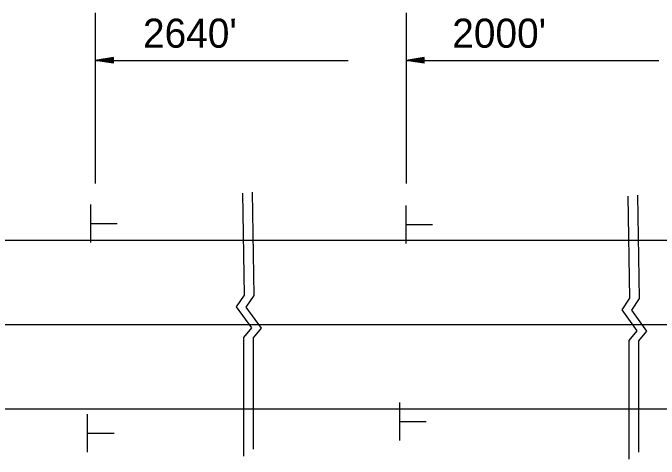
# Model space of a CAD drawing. Extents: x 13528 to 25043, y 7635 to 10612.
# Drawn here: x 16041.5 to 16174.9, y 10266.3 to 10358.4 of the extents above; entities that cross this region are included whole.
import ezdxf

# ---------------------------------------------------------------- set-up
doc = ezdxf.new("R2010")
doc.units = 0
doc.layers.add('Default', color=7, linetype='Continuous')

msp = doc.modelspace()

# ---------------------------------------------------------------- linework, layer by layer
at = {"layer": 'Default'}
for p, q in [((16058.47, 10358.39), (16058.47, 10323.18)), ((16122.63, 10358.39), (16122.63, 10323.18)), ((16062.22, 10349.16), (16058.47, 10348.6)), ((16058.47, 10348.6), (16110.66, 10348.6)), ((16062.22, 10348.04), (16058.47, 10348.6)), ((16062.22, 10349.07), (16059.1, 10348.6)), ((16062.22, 10348.13), (16059.1, 10348.6)), ((16062.22, 10348.97), (16059.74, 10348.6)), ((16062.22, 10348.23), (16059.74, 10348.6)), ((16062.22, 10348.88), (16060.37, 10348.6)), ((16062.22, 10348.32), (16060.37, 10348.6)), ((16062.22, 10348.78), (16061, 10348.6)), ((16062.22, 10348.42), (16061, 10348.6)), ((16062.22, 10348.69), (16061.63, 10348.6)), ((16062.22, 10348.51), (16061.63, 10348.6)), ((16062.22, 10348.04), (16062.22, 10349.16)), ((16126.38, 10349.16), (16122.63, 10348.6)), ((16122.63, 10348.6), (16174.82, 10348.6)), ((16126.38, 10348.04), (16122.63, 10348.6)), ((16126.38, 10349.07), (16123.26, 10348.6)), ((16126.38, 10348.13), (16123.26, 10348.6)), ((16126.38, 10348.97), (16123.9, 10348.6)), ((16126.38, 10348.23), (16123.9, 10348.6)), ((16126.38, 10348.88), (16124.53, 10348.6)), ((16126.38, 10348.32), (16124.53, 10348.6)), ((16126.38, 10348.78), (16125.16, 10348.6)), ((16126.38, 10348.42), (16125.16, 10348.6)), ((16126.38, 10348.69), (16125.79, 10348.6)), ((16126.38, 10348.51), (16125.79, 10348.6)), ((16126.38, 10348.04), (16126.38, 10349.16)), ((16057.56, 10311.04), (16057.56, 10318.87)), ((16122.63, 10310.81), (16122.63, 10318.63)), ((16057.68, 10314.94), (16063.02, 10314.94)), ((16122.75, 10314.7), (16128.09, 10314.7)), ((16020.49, 10311.48), (16082.46, 10311.48)), ((16082.46, 10311.48), (16143.31, 10311.48)), ((16143.31, 10311.48), (16229.91, 10311.48)), ((16020.95, 10294.1), (16082.12, 10294.1)), ((16082.12, 10294.1), (16143.31, 10294.1)), ((16143.31, 10294.1), (16229.91, 10294.1)), ((16121.37, 10270.17), (16121.37, 10277.99)), ((16021.41, 10276.71), (16081.79, 10276.71)), ((16081.79, 10276.71), (16156.13, 10276.71)), ((16143.31, 10276.71), (16239.09, 10276.71)), ((16056.88, 10267.78), (16056.88, 10275.61)), ((16121.48, 10274.06), (16126.82, 10274.06)), ((16057, 10271.67), (16062.34, 10271.67))]:
    msp.add_line(p, q, dxfattribs=at)
for points in [[(16088.89, 10321.19), (16089.21, 10300.15), (16087.58, 10297.74), (16090.75, 10293.41), (16089.08, 10291.41), (16089.08, 10266.95)], [(16090.88, 10321.38), (16091.21, 10300.07), (16089.58, 10297.66), (16092.75, 10293.33), (16091.08, 10291.33), (16091.08, 10268.36)], [(16168.45, 10320.56), (16168.77, 10299.52), (16167.15, 10297.11), (16170.31, 10292.78), (16168.65, 10290.78), (16168.64, 10266.32)], [(16170.45, 10320.75), (16170.77, 10299.44), (16169.15, 10297.03), (16172.31, 10292.7), (16170.64, 10290.7), (16170.64, 10267.73)]]:
    msp.add_lwpolyline(points, dxfattribs=at)

# ---------------------------------------------------------------- texts
for s, p in [("2640'", (16068.32, 10351.21)), ("2000'", (16132.17, 10351.21))]:
    msp.add_text(s, height=6, dxfattribs=at).set_placement(p)

doc.saveas('drawing.dxf')
